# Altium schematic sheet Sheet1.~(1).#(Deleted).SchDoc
size A3; SheetNumber: 2; SheetTotal: 2
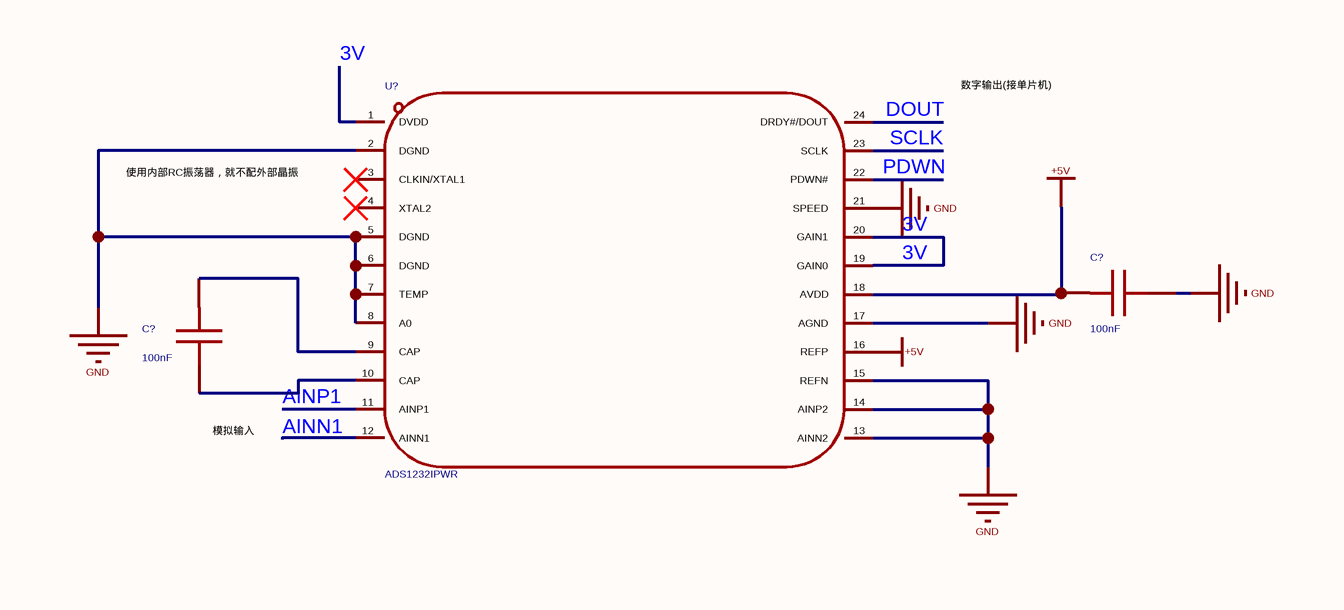
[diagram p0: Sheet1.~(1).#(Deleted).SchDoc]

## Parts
(Parts that share a designator on the sheet are numbered #1, #2 ... from top to bottom, then left to right.)
C?#1  100nF  [C0603]
C?#2  100nF  [C0603]
U?  ADS1232IPWR  [TSSOP-24_L7.8-W4.4-P0.65-LS6.4-BL]

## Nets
+5V: C?#1.2 U?.16(REFP) U?.18(AVDD)
GND: C?#1.1 U?.2(DGND) U?.5(DGND) U?.6(DGND) U?.7(TEMP) U?.8(A0) U?.13(AINN2) U?.14(AINP2) U?.15(REFN) U?.17(AGND) U?.21(SPEED)
3V: U?.1(DVDD) U?.19(GAIN0) U?.20(GAIN1)
AINN1: U?.12(AINN1)
AINP1: U?.11(AINP1)
DOUT: U?.24(DRDY#/DOUT)
PDWN: U?.22(PDWN#)
SCLK: U?.23(SCLK)
NetC?#2_1: C?#2.1 U?.10(CAP)
NetC?#2_2: C?#2.2 U?.9(CAP)

Not connected (* = marked no-connect by the designer): U? 3(CLKIN/XTAL1)* 4(XTAL2)*

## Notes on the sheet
- 使用内部RC振荡器，就不配外部晶振
- 数字输出(接单片机)
- (near C?#2) 模拟输入

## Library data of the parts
C?#1 C?#2 = CAP_0603: Symbol: Capacitance; ConvertToPcb: yes; ModelId: ac125912035d415993ca9572d50418b1聨0819f05c4eef4c71ace90d822a990e87; ModelName: C0603_L1.6-W0.8-H0.8; ModelTransform: 62.992,31.496,0,0,0,0,0,0,0
U? = ADS1232IPWR: 分辨率(位):24;采样率:10Hz;工作电压:2.7V~5.3V;接口类型:SPI;; Manufacturer: TI(德州仪器); AddInBom: yes; ModelId: 57e278220af748a2882c4abba4094eb9聨0819f05c4eef4c71ace90d822a990e87; ModelName: TSSOP-24_L7.8-W4.4-H1.0-LS6.4-P0.65; ModelTransform: 252.188,307.086,0,90,0,0,0,0,0; Resolution (Bits): 24; Sampling Rate: 10Hz; number of channels: 2; Interface: SPI; differential input: 是; Clock/Oscillator: 内置；外置; Clock Frequency: 4.9152MHz；200kHz~8MHz; Voltage Reference: 外置; Programmable Gain: 支持; Temperature Sensors: 内置; ADC architecture: Sigma-Delta; Data rate: 80Hz；10Hz; Quiescent Current (Iq): 1.3uA; Full-Scale Range(FSR): 39mV；1.25V；19.5mV；2.5V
